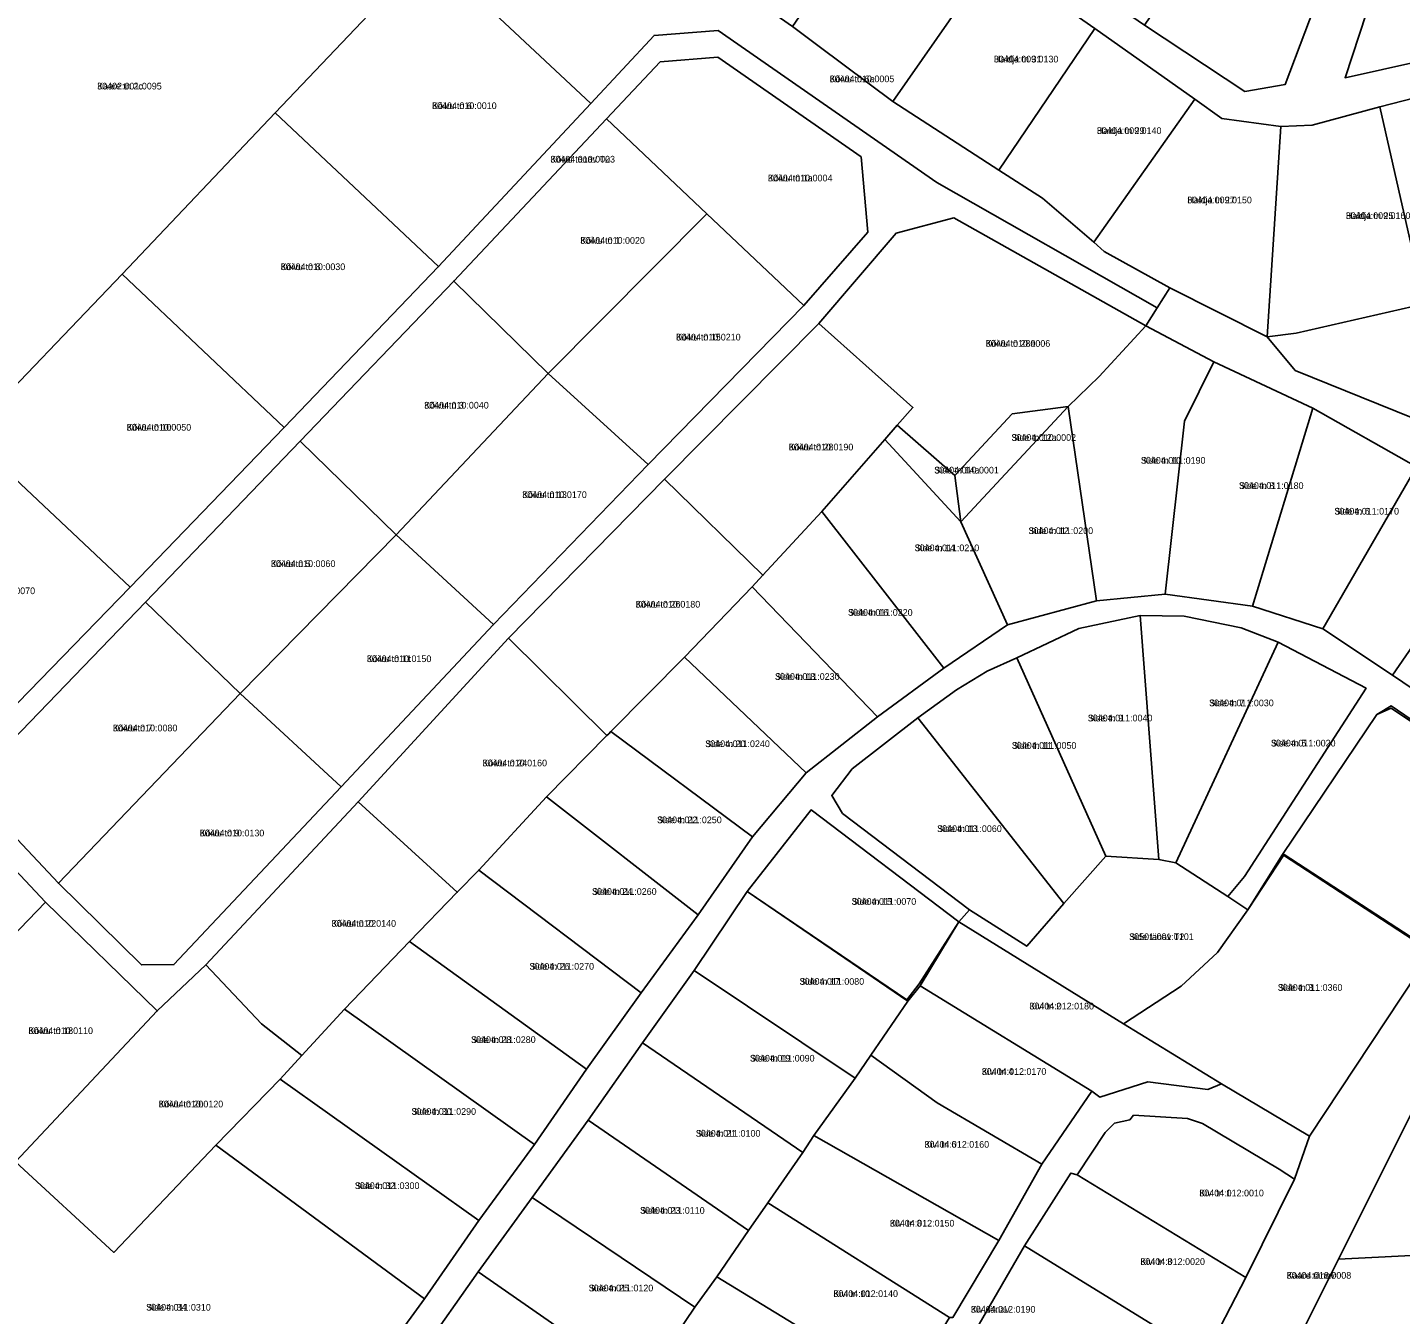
# Model space of a CAD drawing. Extents: x 542681 to 554572, y 6566489 to 6580482.
# Drawn here: x 543954 to 544262.4, y 6576162.5 to 6576451.7 of the extents above; entities that cross this region are included whole.
import ezdxf

# ---------------------------------------------------------------- set-up
doc = ezdxf.new("R2010")
doc.units = 0
for name, color, linetype in [('L_AADRESS', 7, 'Continuous'), ('PIIR', 7, 'Continuous'), ('TUNNUS', 7, 'Continuous')]:
    doc.layers.add(name, color=color, linetype=linetype)

msp = doc.modelspace()

# ---------------------------------------------------------------- linework, layer by layer
at = {"layer": 'PIIR'}
for points in [[(544286.61, 6576441.29), (544257.79, 6576433.83), (544242.57, 6576429.7), (544235.52, 6576429.45), (544222.25, 6576431.22), (544216.21, 6576435.56), (544193.76, 6576451.43), (544170.89, 6576467.39), (544147.64, 6576483.61), (544124.67, 6576499.26), (544128.83, 6576505.05), (544137.15, 6576499.41), (544157.82, 6576512.98), (544182.59, 6576528.83), (544208.09, 6576544.83), (544233.35, 6576561), (544258.69, 6576578.28), (544261.23, 6576579.8), (544289.09, 6576597.81)], [(544262.49, 6576571.37), (544239.79, 6576556.86), (544210.12, 6576537.92), (544174.56, 6576514.35), (544160.49, 6576504.28), (544156.37, 6576501.1), (544150.76, 6576494.53), (544150.8, 6576490.14), (544179.63, 6576469.59), (544204.88, 6576452.2), (544227.47, 6576437.3), (544236.48, 6576438.83), (544245.33, 6576462.28), (544257.69, 6576496.4), (544259.96, 6576502.39), (544262.2, 6576501.99), (544265.96, 6576489.08), (544249.95, 6576440.39), (544282.82, 6576447.7)], [(544009.15, 6576119.22), (544043.16, 6576166.01), (544055.4, 6576183.59), (544067.88, 6576200.69), (544079.55, 6576217.58), (544091.82, 6576234.79), (544104.65, 6576252.32), (544116.86, 6576269.8), (544128.88, 6576284.19), (544144.92, 6576296.77), (544159.86, 6576307.73), (544174.13, 6576317.44), (544194.1, 6576322.86), (544209.55, 6576324.37), (544229.17, 6576321.66), (544244.97, 6576316.55), (544260.61, 6576306.15), (544296.12, 6576282.1)], [(544292.94, 6576276.91), (544260.31, 6576298.73), (544257.08, 6576297.28), (544235.91, 6576265.86), (544228.15, 6576253.42), (544223.59, 6576256.44), (544227.38, 6576260.92), (544254.67, 6576303.22), (544234.9, 6576313.55), (544226.59, 6576316.75), (544213.8, 6576319.4), (544203.95, 6576319.54), (544190.16, 6576316.61), (544176.24, 6576310.03), (544169.56, 6576307.05), (544162.71, 6576302.86), (544154.01, 6576296.57), (544139.28, 6576285.11), (544134.65, 6576279.07), (544137.04, 6576275.08), (544165.63, 6576253.39), (544163.17, 6576250.74), (544130.01, 6576275.87), (544115.69, 6576257.54), (544103.77, 6576239.77), (544092.12, 6576223.51), (544079.95, 6576206.12), (544067.39, 6576188.74), (544055.21, 6576172.06), (544042.61, 6576154.11)], [(544218.42, 6576152.97), (544227.68, 6576170.79), (544238.61, 6576192.93), (544241.94, 6576202.52), (544269.55, 6576244.2)], [(544161.88, 6576161.84), (544172.2, 6576179.15), (544181.87, 6576196.29), (544193.09, 6576212.64), (544194.87, 6576211.32), (544205.63, 6576214.75), (544219.11, 6576213.06), (544222.23, 6576214.33), (544241.94, 6576202.52), (544238.61, 6576192.93), (544235.14, 6576195.16), (544217.94, 6576205.38), (544214.59, 6576206.52), (544202.46, 6576207.27), (544201.63, 6576206.24), (544198.19, 6576205.49), (544196.1, 6576203.4), (544189.79, 6576193.88), (544188.39, 6576194.26), (544177.97, 6576177.9), (544167.75, 6576160.33)], [(544269.27, 6576216.57), (544248.48, 6576174.91), (544240.49, 6576158.91)]]:
    msp.add_lwpolyline(points, dxfattribs=at)
for points in [[(543870.87, 6576403.95), (544085.24, 6576538.48), (544097.38, 6576527.56), (544064.6, 6576491.86), (544064.17, 6576490.1), (544044.07, 6576468.75), (544009.62, 6576432.52), (543975.25, 6576396.23), (543940.66, 6576360.15), (543918.54, 6576337.02)], [(544259.96, 6576502.39), (544260.82, 6576504.94), (544268.65, 6576492.64), (544260.11, 6576467.58), (544285.27, 6576449.45), (544282.82, 6576447.7), (544249.95, 6576440.39), (544265.96, 6576489.08), (544262.2, 6576501.99)], [(544044.07, 6576468.75), (544064.17, 6576490.1), (544066.59, 6576489.13), (544097.22, 6576471.39), (544102.48, 6576468.22), (544125.81, 6576451.93), (544131.83, 6576447.39), (544148.37, 6576435.01), (544172.2, 6576419.65), (544181.99, 6576413.35), (544193.51, 6576403.42), (544195.85, 6576401.34), (544210.63, 6576393.14), (544207.76, 6576388.65), (544158.24, 6576416.83), (544109.18, 6576451), (544094.74, 6576449.9), (544080.52, 6576434.57)], [(544125.81, 6576451.93), (544147.64, 6576483.61), (544170.89, 6576467.39), (544148.37, 6576435.01), (544131.83, 6576447.39)], [(544221.28, 6576476.4), (544245.33, 6576462.28), (544236.48, 6576438.83), (544227.47, 6576437.3), (544204.88, 6576452.2)], [(544009.62, 6576432.52), (544044.07, 6576468.75), (544080.52, 6576434.57), (544046.36, 6576397.94)], [(544148.37, 6576435.01), (544170.89, 6576467.39), (544193.76, 6576451.43), (544172.2, 6576419.65)], [(543935.19, 6576279.37), (543936.66, 6576284.38), (543977.09, 6576325.95), (544011.69, 6576361.81), (544046.36, 6576397.94), (544080.52, 6576434.57), (544094.74, 6576449.9), (544109.18, 6576451), (544158.24, 6576416.83), (544207.76, 6576388.65), (544205.21, 6576384.66), (544162.11, 6576408.88), (544149.12, 6576405.45), (544131.72, 6576385.2), (544097.11, 6576350.22), (544062.02, 6576314.43), (544028.25, 6576277.71), (543994.05, 6576241.05), (543983.17, 6576230.7), (543958.09, 6576255.13)], [(544172.2, 6576419.65), (544193.76, 6576451.43), (544216.21, 6576435.56), (544193.51, 6576403.42), (544181.99, 6576413.35)], [(543944.58, 6576285.35), (543944.69, 6576276.68), (543960.96, 6576259.37), (543979.61, 6576241.04), (543986.9, 6576241.11), (544024.44, 6576281.04), (544058.69, 6576317.5), (544093.45, 6576353.49), (544128.42, 6576389.19), (544142.76, 6576405.7), (544141.23, 6576422.59), (544109.08, 6576444.98), (544096.12, 6576443.98), (544084.05, 6576431.14), (544049.76, 6576394.71), (544015.25, 6576358.69), (543980.53, 6576322.51)], [(544084.05, 6576431.14), (544096.12, 6576443.98), (544109.08, 6576444.98), (544141.23, 6576422.59), (544142.76, 6576405.7), (544128.42, 6576389.19), (544106.61, 6576409.8)], [(544257.79, 6576433.83), (544286.61, 6576441.29), (544291.27, 6576393.78), (544284.48, 6576393.2), (544267.8, 6576389.6)], [(544193.51, 6576403.42), (544216.21, 6576435.56), (544222.25, 6576431.22), (544235.52, 6576429.45), (544232.45, 6576382.15), (544210.63, 6576393.14), (544195.85, 6576401.34)], [(544232.45, 6576382.15), (544235.52, 6576429.45), (544242.57, 6576429.7), (544257.79, 6576433.83), (544267.8, 6576389.6), (544238.95, 6576382.96)], [(544009.62, 6576432.52), (544046.36, 6576397.94), (544011.69, 6576361.81), (543975.25, 6576396.23)], [(544070.96, 6576373.96), (544049.76, 6576394.71), (544084.05, 6576431.14), (544106.61, 6576409.8)], [(544128.42, 6576389.19), (544093.45, 6576353.49), (544070.96, 6576373.96), (544106.61, 6576409.8)], [(544131.72, 6576385.2), (544149.12, 6576405.45), (544162.11, 6576408.88), (544205.21, 6576384.66), (544194.75, 6576373.29), (544187.76, 6576366.55), (544175.16, 6576364.86), (544162.3, 6576351), (544149.36, 6576362.35), (544152.89, 6576366.3)], [(543940.66, 6576360.15), (543975.25, 6576396.23), (544011.69, 6576361.81), (543977.09, 6576325.95)], [(544015.25, 6576358.69), (544049.76, 6576394.71), (544070.96, 6576373.96), (544036.81, 6576337.65)], [(544232.45, 6576382.15), (544238.95, 6576382.96), (544267.8, 6576389.6), (544284.48, 6576393.2), (544291.27, 6576393.78), (544314.88, 6576394.77), (544301.19, 6576374.86), (544287.46, 6576354.91), (544238.75, 6576374.62)], [(544210.63, 6576393.14), (544232.45, 6576382.15), (544238.75, 6576374.62), (544287.46, 6576354.91), (544336.17, 6576335.2), (544326.02, 6576321.24), (544285.57, 6576342.34), (544265.98, 6576352.98), (544242.72, 6576366.15), (544220.47, 6576376.55), (544205.21, 6576384.66), (544207.76, 6576388.65)], [(544097.11, 6576350.22), (544131.72, 6576385.2), (544152.89, 6576366.3), (544149.36, 6576362.35), (544146.59, 6576359.09), (544132.42, 6576342.92), (544119.19, 6576328.6)], [(544187.76, 6576366.55), (544194.75, 6576373.29), (544205.21, 6576384.66), (544220.47, 6576376.55), (544213.87, 6576363.22), (544209.55, 6576324.37), (544194.1, 6576322.86)], [(544213.87, 6576363.22), (544220.47, 6576376.55), (544242.72, 6576366.15), (544229.17, 6576321.66), (544209.55, 6576324.37)], [(544036.81, 6576337.65), (544070.96, 6576373.96), (544093.45, 6576353.49), (544058.69, 6576317.5)], [(544162.3, 6576351), (544175.16, 6576364.86), (544187.76, 6576366.55), (544163.62, 6576340.58)], [(544163.62, 6576340.58), (544187.76, 6576366.55), (544194.1, 6576322.86), (544174.13, 6576317.44)], [(544242.72, 6576366.15), (544265.98, 6576352.98), (544244.97, 6576316.55), (544229.17, 6576321.66)], [(543914.84, 6576305.8), (543905.34, 6576323.31), (543918.54, 6576337.02), (543940.66, 6576360.15), (543977.09, 6576325.95), (543936.66, 6576284.38)], [(544146.59, 6576359.09), (544149.36, 6576362.35), (544162.3, 6576351), (544163.62, 6576340.58)], [(543980.53, 6576322.51), (544015.25, 6576358.69), (544036.81, 6576337.65), (544001.76, 6576302.04)], [(544146.59, 6576359.09), (544163.62, 6576340.58), (544174.13, 6576317.44), (544159.86, 6576307.73), (544132.42, 6576342.92)], [(544244.97, 6576316.55), (544265.98, 6576352.98), (544285.57, 6576342.34), (544260.61, 6576306.15)], [(544062.02, 6576314.43), (544097.11, 6576350.22), (544119.19, 6576328.6), (544116.78, 6576325.98), (544101.61, 6576310.16), (544085.03, 6576293.45), (544084.55, 6576292.97), (544084.15, 6576292.55)], [(544119.19, 6576328.6), (544132.42, 6576342.92), (544159.86, 6576307.73), (544144.92, 6576296.77), (544116.78, 6576325.98)], [(544285.57, 6576342.34), (544326.02, 6576321.24), (544296.12, 6576282.1), (544260.61, 6576306.15)], [(544058.69, 6576317.5), (544024.44, 6576281.04), (544001.76, 6576302.04), (544036.81, 6576337.65)], [(544116.78, 6576325.98), (544144.92, 6576296.77), (544128.88, 6576284.19), (544101.61, 6576310.16)], [(543944.69, 6576276.68), (543944.58, 6576285.35), (543980.53, 6576322.51), (544001.76, 6576302.04), (543960.96, 6576259.37)], [(544196.22, 6576265.44), (544176.24, 6576310.03), (544190.16, 6576316.61), (544203.95, 6576319.54), (544208.11, 6576264.69)], [(544208.11, 6576264.69), (544203.95, 6576319.54), (544213.8, 6576319.4), (544226.59, 6576316.75), (544234.9, 6576313.55), (544211.96, 6576263.94)], [(544028.25, 6576277.71), (544062.02, 6576314.43), (544084.15, 6576292.55), (544070.6, 6576278.77), (544055.38, 6576262.34), (544050.54, 6576257.36)], [(544211.96, 6576263.94), (544234.9, 6576313.55), (544254.67, 6576303.22), (544227.38, 6576260.92), (544223.59, 6576256.44)], [(544101.61, 6576310.16), (544128.88, 6576284.19), (544116.86, 6576269.8), (544085.03, 6576293.45)], [(544186.75, 6576254.8), (544154.01, 6576296.57), (544162.71, 6576302.86), (544169.56, 6576307.05), (544176.24, 6576310.03), (544196.22, 6576265.44)], [(543986.9, 6576241.11), (543979.61, 6576241.04), (543960.96, 6576259.37), (544001.76, 6576302.04), (544024.44, 6576281.04)], [(544235.91, 6576265.86), (544257.08, 6576297.28), (544260.3, 6576299.22), (544292.94, 6576276.91), (544269.12, 6576244.14)], [(544165.63, 6576253.39), (544137.04, 6576275.08), (544134.65, 6576279.07), (544139.28, 6576285.11), (544154.01, 6576296.57), (544186.75, 6576254.8), (544178.44, 6576245.23)], [(544085.03, 6576293.45), (544116.86, 6576269.8), (544104.65, 6576252.32), (544070.6, 6576278.77), (544084.15, 6576292.55)], [(543899.57, 6576246.77), (543935.19, 6576279.37), (543958.09, 6576255.13), (543925.27, 6576221.13)], [(544006.55, 6576227.81), (543994.05, 6576241.05), (544028.25, 6576277.71), (544050.54, 6576257.36), (544039.79, 6576246.28), (544025.25, 6576231.1), (544015.62, 6576220.65)], [(544070.6, 6576278.77), (544104.65, 6576252.32), (544091.82, 6576234.79), (544055.38, 6576262.34)], [(544115.69, 6576257.54), (544130.01, 6576275.87), (544163.17, 6576250.74), (544154.26, 6576236.77), (544151.51, 6576233.21)], [(544200.17, 6576227.79), (544163.17, 6576250.74), (544165.63, 6576253.39), (544178.44, 6576245.23), (544186.75, 6576254.8), (544196.22, 6576265.44), (544208.11, 6576264.69), (544211.96, 6576263.94), (544223.59, 6576256.44), (544228.15, 6576253.42), (544221.29, 6576243.85), (544213.15, 6576236.23)], [(544222.23, 6576214.33), (544200.17, 6576227.79), (544213.15, 6576236.23), (544221.29, 6576243.85), (544228.15, 6576253.42), (544236.27, 6576265.82), (544269.55, 6576244.2), (544241.94, 6576202.52)], [(544050.54, 6576257.36), (544055.38, 6576262.34), (544091.82, 6576234.79), (544079.55, 6576217.58), (544039.79, 6576246.28)], [(543925.27, 6576221.13), (543958.09, 6576255.13), (543983.17, 6576230.7), (543951.32, 6576196.79), (543939.43, 6576208.34)], [(544115.69, 6576257.54), (544151.74, 6576232.86), (544143.46, 6576220.78), (544139.92, 6576215.59), (544103.77, 6576239.77)], [(544193.09, 6576212.64), (544154.49, 6576236.37), (544163.17, 6576250.74), (544200.17, 6576227.79), (544222.23, 6576214.33), (544219.11, 6576213.06), (544205.63, 6576214.75), (544194.87, 6576211.32)], [(544039.79, 6576246.28), (544079.55, 6576217.58), (544067.88, 6576200.69), (544025.25, 6576231.1)], [(543951.32, 6576196.79), (543983.17, 6576230.7), (543994.05, 6576241.05), (544006.55, 6576227.81), (544015.62, 6576220.65), (544010.73, 6576215.34), (543996.3, 6576200.53), (543973.39, 6576176.45)], [(544128.15, 6576198.87), (544092.12, 6576223.51), (544103.77, 6576239.77), (544139.92, 6576215.59), (544130.62, 6576202.67)], [(544143.46, 6576220.78), (544151.74, 6576232.86), (544154.49, 6576236.37), (544193.09, 6576212.64), (544181.87, 6576196.29), (544158.35, 6576210.06)], [(544015.62, 6576220.65), (544025.25, 6576231.1), (544067.88, 6576200.69), (544055.4, 6576183.59), (544010.73, 6576215.34)], [(544092.12, 6576223.51), (544128.15, 6576198.87), (544120.28, 6576187.57), (544115.93, 6576181.35), (544079.95, 6576206.12)], [(544139.92, 6576215.59), (544143.46, 6576220.78), (544158.35, 6576210.06), (544181.87, 6576196.29), (544172.2, 6576179.15), (544130.62, 6576202.67)], [(544010.73, 6576215.34), (544055.4, 6576183.59), (544043.16, 6576166.01), (543996.3, 6576200.53)], [(544291.75, 6576177.06), (544248.48, 6576174.91), (544269.27, 6576216.57), (544309.48, 6576196.57), (544300.42, 6576176.92), (544295.43, 6576175.19)], [(543939.43, 6576208.34), (543951.32, 6576196.79), (543973.39, 6576176.45), (543996.3, 6576200.53), (544043.16, 6576166.01), (544009.15, 6576119.22), (543984.31, 6576118.38), (543906.78, 6576172.72)], [(544103.91, 6576164.12), (544067.39, 6576188.74), (544079.95, 6576206.12), (544115.93, 6576181.35), (544108.81, 6576170.96)], [(544196.1, 6576203.4), (544198.19, 6576205.49), (544201.63, 6576206.24), (544202.46, 6576207.27), (544214.59, 6576206.52), (544217.94, 6576205.38), (544235.14, 6576195.16), (544238.61, 6576192.93), (544227.68, 6576170.79), (544189.79, 6576193.88)], [(544128.15, 6576198.87), (544130.62, 6576202.67), (544172.2, 6576179.15), (544161.88, 6576161.84), (544161.1, 6576161.82), (544120.28, 6576187.57)], [(544188.39, 6576194.26), (544189.79, 6576193.88), (544227.68, 6576170.79), (544218.42, 6576152.97), (544177.97, 6576177.9)], [(544067.39, 6576188.74), (544103.91, 6576164.12), (544097.55, 6576154.68), (544091.82, 6576146.63), (544055.21, 6576172.06)], [(544115.93, 6576181.35), (544120.28, 6576187.57), (544161.1, 6576161.82), (544150.9, 6576145.26), (544108.81, 6576170.96)], [(544177.97, 6576177.9), (544218.42, 6576152.97), (544209.29, 6576135.03), (544167.75, 6576160.33)], [(544240.49, 6576158.91), (544248.48, 6576174.91), (544291.75, 6576177.06), (544280.65, 6576140.9)], [(544055.21, 6576172.06), (544091.82, 6576146.63), (544082.95, 6576134.05), (544079.5, 6576128.73), (544042.61, 6576154.11)], [(544103.91, 6576164.12), (544108.81, 6576170.96), (544150.9, 6576145.26), (544139.99, 6576128.75), (544097.55, 6576154.68)]]:
    msp.add_lwpolyline(points, close=True, dxfattribs=at)

# ---------------------------------------------------------------- texts
at = {"layer": 'L_AADRESS'}
for s, p in [('Haldja tn 31', (544171.06, 6576443.82)), ('Kõivu tn 6a', (544134.2, 6576439.38)), ('Kaare tn 2c', (543969.66, 6576437.75)), ('Kõivu tn 6', (544044.89, 6576433.35)), ('Haldja tn 29', (544194.21, 6576427.76)), ('Kõivu tänav T2', (544071.47, 6576421.33)), ('Kõivu tn 1a', (544120.32, 6576417.09)), ('Haldja tn 27', (544214.52, 6576412.17)), ('Haldja tn 25', (544250.12, 6576408.64)), ('Kõivu tn 1', (544078.18, 6576403.07)), ('Kõivu tn 8', (544010.88, 6576397.16)), ('Kõivu tn 15', (544099.69, 6576381.35)), ('Kõivu tn 28a', (544169.24, 6576379.94)), ('Kõivu tn 3', (544043.11, 6576366.05)), ('Kõivu tn 10', (543976.28, 6576361.09)), ('Side tn 12a', (544175.03, 6576358.79)), ('Kõivu tn 28', (544125, 6576356.65)), ('Side tn 10', (544204.11, 6576353.65)), ('Side tn 14a', (544157.69, 6576351.46)), ('Kõivu tn 13', (544065.13, 6576345.96)), ('Side tn 8', (544226.13, 6576347.99)), ('Side tn 6', (544247.57, 6576342.23)), ('Side tn 12', (544178.86, 6576337.85)), ('Side tn 14', (544153.28, 6576334)), ('Kõivu tn 5', (544008.67, 6576330.45)), ('Kõivu tn 26', (544090.61, 6576321.33)), ('Side tn 16', (544138.32, 6576319.49)), ('Kõivu tn 11', (544030.22, 6576309.08)), ('Side tn 18', (544121.92, 6576305.09)), ('Side tn 7', (544219.43, 6576299.16)), ('Kõivu tn 7', (543973.17, 6576293.52)), ('Side tn 9', (544192.18, 6576295.75)), ('Side tn 20', (544106.25, 6576289.98)), ('Side tn 11', (544175.11, 6576289.59)), ('Side tn 5', (544233.32, 6576290.12)), ('Kõivu tn 24', (544056.2, 6576285.66)), ('Side tn 22', (544095.44, 6576272.88)), ('Kõivu tn 9', (543992.7, 6576269.92)), ('Side tn 13', (544158.34, 6576270.9)), ('Side tn 24', (544080.82, 6576256.78)), ('Side tn 15', (544139.13, 6576254.54)), ('Kõivu tn 22', (544022.29, 6576249.61)), ('Side tänav T2', (544201.46, 6576246.62)), ('Side tn 26', (544066.76, 6576239.96)), ('Side tn 17', (544127.44, 6576236.57)), ('Side tn 3', (544234.86, 6576235.21)), ('Kivi tn 2', (544179.06, 6576231.03)), ('Kõivu tn 18', (543954.22, 6576225.5)), ('Side tn 28', (544053.65, 6576223.49)), ('Side tn 19', (544116.3, 6576219.32)), ('Kivi tn 4', (544168.36, 6576216.33)), ('Kõivu tn 20', (543983.47, 6576209.02)), ('Side tn 30', (544040.26, 6576207.35)), ('Side tn 21', (544104.13, 6576202.43)), ('Kivi tn 6', (544155.5, 6576199.96)), ('Side tn 32', (544027.55, 6576190.68)), ('Kivi tn 1', (544217.22, 6576189.03)), ('Side tn 23', (544091.61, 6576185.12)), ('Kivi tn 8', (544147.72, 6576182.25)), ('Kivi tn 3', (544203.98, 6576173.62)), ('Kaare tänav', (544236.84, 6576170.53)), ('Side tn 25', (544080.07, 6576167.68)), ('Kivi tn 10', (544135.03, 6576166.42)), ('Side tn 34', (543980.68, 6576163.36)), ('Kivi tänav', (544165.9, 6576162.9))]:
    msp.add_text(s, height=1.5, dxfattribs=at).set_placement(p)
at = {"layer": 'TUNNUS'}
for s, p in [('30404:009:0130', (544171.06, 6576443.82)), ('30404:010:0005', (544134.2, 6576439.38)), ('30402:001:0095', (543969.66, 6576437.75)), ('30404:010:0010', (544044.89, 6576433.35)), ('30404:009:0140', (544194.21, 6576427.76)), ('30404:010:0003', (544071.47, 6576421.33)), ('30404:010:0004', (544120.32, 6576417.09)), ('30404:009:0150', (544214.52, 6576412.17)), ('30404:009:0160', (544250.12, 6576408.64)), ('30404:010:0020', (544078.18, 6576403.07)), ('30404:010:0030', (544010.88, 6576397.16)), ('30404:010:0210', (544099.69, 6576381.35)), ('30404:010:0006', (544169.24, 6576379.94)), ('30404:010:0040', (544043.11, 6576366.05)), ('30404:010:0050', (543976.28, 6576361.09)), ('30404:010:0002', (544175.03, 6576358.79)), ('30404:010:0190', (544125, 6576356.65)), ('30404:011:0190', (544204.11, 6576353.65)), ('30404:010:0001', (544157.69, 6576351.46)), ('30404:010:0170', (544065.13, 6576345.96)), ('30404:011:0180', (544226.13, 6576347.99)), ('30404:011:0170', (544247.57, 6576342.23)), ('30404:011:0200', (544178.86, 6576337.85)), ('30404:011:0210', (544153.28, 6576334)), ('30404:010:0060', (544008.67, 6576330.45)), ('30404:010:0070', (543941.22, 6576324.35)), ('30404:010:0180', (544090.61, 6576321.33)), ('30404:011:0220', (544138.32, 6576319.49)), ('30404:010:0150', (544030.22, 6576309.08)), ('30404:011:0230', (544121.92, 6576305.09)), ('30404:011:0030', (544219.43, 6576299.16)), ('30404:010:0080', (543973.17, 6576293.52)), ('30404:011:0040', (544192.18, 6576295.75)), ('30404:011:0240', (544106.25, 6576289.98)), ('30404:011:0050', (544175.11, 6576289.59)), ('30404:011:0020', (544233.32, 6576290.12)), ('30404:010:0160', (544056.2, 6576285.66)), ('30404:011:0250', (544095.44, 6576272.88)), ('30404:010:0130', (543992.7, 6576269.92)), ('30404:011:0060', (544158.34, 6576270.9)), ('30404:011:0260', (544080.82, 6576256.78)), ('30404:011:0070', (544139.13, 6576254.54)), ('30404:010:0140', (544022.29, 6576249.61)), ('30501:001:0101', (544201.46, 6576246.62)), ('30404:011:0270', (544066.76, 6576239.96)), ('30404:011:0080', (544127.44, 6576236.57)), ('30404:011:0360', (544234.86, 6576235.21)), ('30404:012:0180', (544179.06, 6576231.03)), ('30404:010:0110', (543954.22, 6576225.5)), ('30404:011:0280', (544053.65, 6576223.49)), ('30404:011:0090', (544116.3, 6576219.32)), ('30404:012:0170', (544168.36, 6576216.33)), ('30404:010:0120', (543983.47, 6576209.02)), ('30404:011:0290', (544040.26, 6576207.35)), ('30404:011:0100', (544104.13, 6576202.43)), ('30404:012:0160', (544155.5, 6576199.96)), ('30404:011:0300', (544027.55, 6576190.68)), ('30404:012:0010', (544217.22, 6576189.03)), ('30404:011:0110', (544091.61, 6576185.12)), ('30404:012:0150', (544147.72, 6576182.25)), ('30404:012:0020', (544203.98, 6576173.62)), ('30404:018:0008', (544236.84, 6576170.53)), ('30404:011:0120', (544080.07, 6576167.68)), ('30404:012:0140', (544135.03, 6576166.42)), ('30404:011:0310', (543980.68, 6576163.36)), ('30404:012:0190', (544165.9, 6576162.9))]:
    msp.add_text(s, height=1.5, dxfattribs=at).set_placement(p)

doc.saveas('drawing.dxf')
